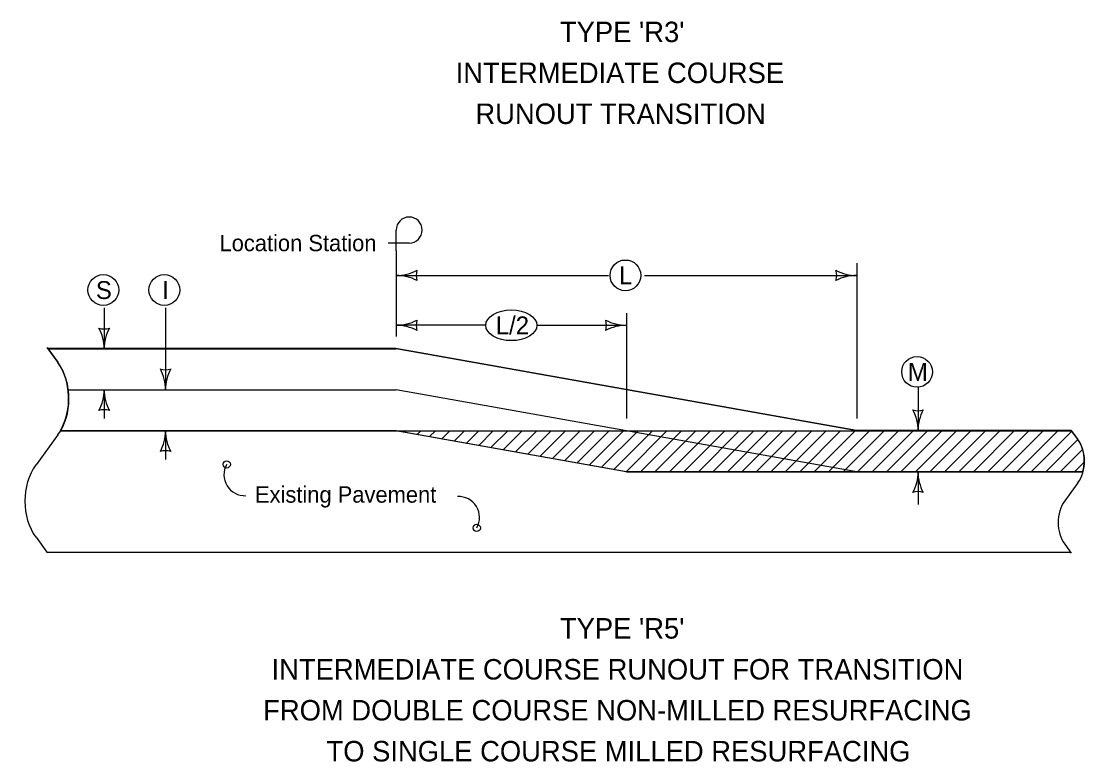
# Model space of a CAD drawing. Extents: x 10133 to 81668, y 2218 to 11018.
# Drawn here: x 19016 to 20057, y 2367 to 3091 of the extents above; entities that cross this region are included whole.
import ezdxf

# ---------------------------------------------------------------- set-up
doc = ezdxf.new("R2010")
doc.units = 0
for name, color, linetype in [('dsnNonPlotable', 7, 'Continuous'), ('dsnShtPlotShapeBatchPrint', 7, 'Continuous'), ('dsnStdBlock', 7, 'Continuous'), ('dsnStdBlockNotModified', 7, 'Continuous')]:
    doc.layers.add(name, color=color, linetype=linetype)

msp = doc.modelspace()

# ---------------------------------------------------------------- linework, layer by layer
at = {"layer": 'dsnNonPlotable'}
for p, q in [((19381.7, 2771.1), (19041.4, 2771.1)), ((19041.4, 2771.1), (19051.2, 2757.7)), ((19381.7, 2771.1), (19041.4, 2771.1)), ((19041.4, 2771.1), (19051.2, 2757.7)), ((19831.7, 2691.1), (19381.7, 2771.1)), ((19831.7, 2691.1), (19381.7, 2771.1)), ((19053.9, 2691.1), (19381.7, 2691.1)), ((19053.9, 2691.1), (19381.7, 2691.1)), ((19381.7, 2691.1), (19606.7, 2651.1)), ((19381.7, 2691.1), (19606.7, 2651.1)), ((20041.7, 2691.1), (19831.7, 2691.1)), ((20041.7, 2691.1), (19831.7, 2691.1)), ((20048, 2682.6), (20041.7, 2691.1)), ((20048, 2682.6), (20041.7, 2691.1)), ((19606.7, 2651.1), (20053.1, 2651.1)), ((19606.7, 2651.1), (20053.1, 2651.1))]:
    msp.add_line(p, q, dxfattribs=at)
for centre, major_axis, ratio, start_param in [((19025.3, 2722.4), (0, -50), 0.732645, 0.89539), ((19025.3, 2722.4), (0, -50), 0.732645, 0.89539), ((20032.4, 2661.4), (0, -30), 0.73263, 1.219806), ((20032.4, 2661.4), (0, -30), 0.73263, 1.219806)]:
    msp.add_ellipse(centre, major_axis=major_axis, ratio=ratio, start_param=start_param, end_param=2.356194, dxfattribs=at)
at = {"layer": 'dsnStdBlock'}
for p, q in [((19382, 2866.6), (19382, 2886.9)), ((19382, 2866.6), (19382, 2886.9)), ((19394.7, 2874.2), (19374.3, 2874.2)), ((19394.7, 2874.2), (19374.3, 2874.2)), ((19382, 2866.6), (19382, 2782.8)), ((19382, 2866.6), (19382, 2782.8)), ((19832, 2854.6), (19832, 2702.8)), ((19832, 2854.6), (19832, 2702.8)), ((19382, 2842.6), (19589.5, 2842.6)), ((19382, 2842.6), (19589.5, 2842.6)), ((19624.5, 2842.6), (19832, 2842.6)), ((19624.5, 2842.6), (19832, 2842.6)), ((19096.6, 2810.8), (19096.6, 2770.8)), ((19096.6, 2810.8), (19096.6, 2770.8)), ((19156.6, 2810.8), (19156.6, 2730.8)), ((19156.6, 2810.8), (19156.6, 2730.8)), ((19607, 2805.8), (19607, 2702.8)), ((19607, 2805.8), (19607, 2702.8)), ((19469.5, 2793.8), (19382, 2793.8)), ((19469.5, 2793.8), (19382, 2793.8)), ((19519.5, 2793.8), (19607, 2793.8)), ((19519.5, 2793.8), (19607, 2793.8)), ((19040.7, 2772), (19051.4, 2757.4)), ((19040.7, 2772), (19051.4, 2757.4)), ((19041.6, 2770.8), (19382, 2770.8)), ((19041.6, 2770.8), (19382, 2770.8)), ((19832, 2690.8), (19382, 2770.8)), ((19832, 2690.8), (19382, 2770.8)), ((19061.6, 2730.8), (19382, 2730.8)), ((19061.6, 2730.8), (19382, 2730.8)), ((19096.6, 2730.8), (19096.6, 2702.8)), ((19096.6, 2730.8), (19096.6, 2702.8)), ((19832, 2650.8), (19382, 2730.8)), ((19832, 2650.8), (19382, 2730.8)), ((19892, 2733.3), (19892, 2690.8)), ((19892, 2733.3), (19892, 2690.8)), ((19051.4, 2686.7), (19030, 2657.4)), ((19051.4, 2686.7), (19030, 2657.4)), ((19054.1, 2690.8), (19382, 2690.8)), ((19054.1, 2690.8), (19382, 2690.8)), ((19156.6, 2690.8), (19156.6, 2662.8)), ((19156.6, 2690.8), (19156.6, 2662.8)), ((19607, 2650.8), (19382, 2690.8)), ((19382, 2690.8), (19832, 2690.8)), ((19607, 2650.8), (19382, 2690.8)), ((19382, 2690.8), (19832, 2690.8)), ((19390.6, 2689.3), (19392.1, 2690.8)), ((19390.6, 2689.3), (19392.1, 2690.8)), ((19402.6, 2687.1), (19406.2, 2690.8)), ((19402.6, 2687.1), (19406.2, 2690.8)), ((19414.6, 2685), (19420.4, 2690.8)), ((19414.6, 2685), (19420.4, 2690.8)), ((19426.6, 2682.9), (19434.5, 2690.8)), ((19426.6, 2682.9), (19434.5, 2690.8)), ((19438.6, 2680.7), (19448.6, 2690.8)), ((19438.6, 2680.7), (19448.6, 2690.8)), ((19450.6, 2678.6), (19462.8, 2690.8)), ((19450.6, 2678.6), (19462.8, 2690.8)), ((19462.6, 2676.5), (19476.9, 2690.8)), ((19462.6, 2676.5), (19476.9, 2690.8)), ((19474.6, 2674.3), (19491.1, 2690.8)), ((19474.6, 2674.3), (19491.1, 2690.8)), ((19486.6, 2672.2), (19505.2, 2690.8)), ((19486.6, 2672.2), (19505.2, 2690.8)), ((19498.6, 2670.1), (19519.4, 2690.8)), ((19498.6, 2670.1), (19519.4, 2690.8)), ((19510.6, 2667.9), (19533.5, 2690.8)), ((19510.6, 2667.9), (19533.5, 2690.8)), ((19522.6, 2665.8), (19547.6, 2690.8)), ((19522.6, 2665.8), (19547.6, 2690.8)), ((19534.6, 2663.6), (19561.8, 2690.8)), ((19534.6, 2663.6), (19561.8, 2690.8)), ((19546.6, 2661.5), (19575.9, 2690.8)), ((19546.6, 2661.5), (19575.9, 2690.8)), ((19558.7, 2659.4), (19590.1, 2690.8)), ((19558.7, 2659.4), (19590.1, 2690.8)), ((19570.7, 2657.2), (19604.2, 2690.8)), ((19570.7, 2657.2), (19604.2, 2690.8)), ((19582.7, 2655.1), (19618.4, 2690.8)), ((19582.7, 2655.1), (19618.4, 2690.8)), ((19594.7, 2653), (19632.5, 2690.8)), ((19594.7, 2653), (19632.5, 2690.8)), ((19606.7, 2650.8), (19646.6, 2690.8)), ((19606.7, 2650.8), (19646.6, 2690.8)), ((19620.8, 2650.8), (19660.8, 2690.8)), ((19620.8, 2650.8), (19660.8, 2690.8)), ((19634.9, 2650.8), (19674.9, 2690.8)), ((19634.9, 2650.8), (19674.9, 2690.8)), ((19649.1, 2650.8), (19689.1, 2690.8)), ((19649.1, 2650.8), (19689.1, 2690.8)), ((19663.2, 2650.8), (19703.2, 2690.8)), ((19663.2, 2650.8), (19703.2, 2690.8)), ((19677.3, 2650.8), (19717.3, 2690.8)), ((19677.3, 2650.8), (19717.3, 2690.8)), ((19691.5, 2650.8), (19731.5, 2690.8)), ((19691.5, 2650.8), (19731.5, 2690.8)), ((19705.6, 2650.8), (19745.6, 2690.8)), ((19705.6, 2650.8), (19745.6, 2690.8)), ((19719.8, 2650.8), (19759.8, 2690.8)), ((19719.8, 2650.8), (19759.8, 2690.8)), ((19733.9, 2650.8), (19773.9, 2690.8)), ((19733.9, 2650.8), (19773.9, 2690.8)), ((19748.1, 2650.8), (19788.1, 2690.8)), ((19748.1, 2650.8), (19788.1, 2690.8)), ((19762.2, 2650.8), (19802.2, 2690.8)), ((19762.2, 2650.8), (19802.2, 2690.8)), ((19776.3, 2650.8), (19816.3, 2690.8)), ((19776.3, 2650.8), (19816.3, 2690.8)), ((19790.5, 2650.8), (19830.5, 2690.8)), ((19790.5, 2650.8), (19830.5, 2690.8)), ((19804.6, 2650.8), (19844.6, 2690.8)), ((19804.6, 2650.8), (19844.6, 2690.8)), ((19818.8, 2650.8), (19858.8, 2690.8)), ((19818.8, 2650.8), (19858.8, 2690.8)), ((19832, 2690.8), (20042, 2690.8)), ((19832, 2690.8), (20042, 2690.8)), ((19832.9, 2650.8), (19872.9, 2690.8)), ((19832.9, 2650.8), (19872.9, 2690.8)), ((19847.1, 2650.8), (19887.1, 2690.8)), ((19847.1, 2650.8), (19887.1, 2690.8)), ((19861.2, 2650.8), (19901.2, 2690.8)), ((19861.2, 2650.8), (19901.2, 2690.8)), ((19875.3, 2650.8), (19915.3, 2690.8)), ((19875.3, 2650.8), (19915.3, 2690.8)), ((19889.5, 2650.8), (19929.5, 2690.8)), ((19889.5, 2650.8), (19929.5, 2690.8)), ((19903.6, 2650.8), (19943.6, 2690.8)), ((19903.6, 2650.8), (19943.6, 2690.8)), ((19917.8, 2650.8), (19957.8, 2690.8)), ((19917.8, 2650.8), (19957.8, 2690.8)), ((19931.9, 2650.8), (19971.9, 2690.8)), ((19931.9, 2650.8), (19971.9, 2690.8)), ((19946, 2650.8), (19986, 2690.8)), ((19946, 2650.8), (19986, 2690.8)), ((19960.2, 2650.8), (20000.2, 2690.8)), ((19960.2, 2650.8), (20000.2, 2690.8)), ((19974.3, 2650.8), (20014.3, 2690.8)), ((19974.3, 2650.8), (20014.3, 2690.8)), ((19988.5, 2650.8), (20028.5, 2690.8)), ((19988.5, 2650.8), (20028.5, 2690.8)), ((20002.6, 2650.8), (20042.6, 2690.8)), ((20002.6, 2650.8), (20042.6, 2690.8)), ((20041.7, 2691.1), (20048.2, 2682.3)), ((20041.7, 2691.1), (20048.2, 2682.3)), ((20016.8, 2650.8), (20048.2, 2682.3)), ((20016.8, 2650.8), (20048.2, 2682.3)), ((20030.9, 2650.8), (20052.9, 2672.8)), ((20030.9, 2650.8), (20052.9, 2672.8)), ((20045, 2650.8), (20054.6, 2660.4)), ((20045, 2650.8), (20054.6, 2660.4)), ((19607, 2650.8), (20053.3, 2650.8)), ((19607, 2650.8), (20053.3, 2650.8)), ((19892, 2650.8), (19892, 2618.8)), ((19892, 2650.8), (19892, 2618.8)), ((20048.2, 2639.9), (20035.3, 2622.3)), ((20048.2, 2639.9), (20035.3, 2622.3)), ((19030, 2586.7), (19040.7, 2572)), ((19030, 2586.7), (19040.7, 2572)), ((19040.7, 2572), (20041.1, 2572)), ((19040.7, 2572), (20041.1, 2572)), ((20035.3, 2579.9), (20041.7, 2571.1)), ((20035.3, 2579.9), (20041.7, 2571.1))]:
    msp.add_line(p, q, dxfattribs=at)
for centre, radius in [((19606, 2842.6), 15), ((19606, 2842.6), 15), ((19095.8, 2828.3), 15), ((19095.8, 2828.3), 15), ((19155.4, 2828.3), 15), ((19155.4, 2828.3), 15), ((19891, 2748.3), 15), ((19891, 2748.3), 15), ((19216.4, 2657.9), 3.56), ((19216.4, 2657.9), 3.56), ((19460.7, 2595.8), 3.56), ((19460.7, 2595.8), 3.56)]:
    msp.add_circle(centre, radius, dxfattribs=at)
for centre, radius, start, end in [((19394.7, 2886.9), 12.7, 270, 180), ((19394.7, 2886.9), 12.7, 270, 180), ((19382, 2885.7), 43.2, 270, 298.0725), ((19382, 2885.7), 43.2, 270, 298.0725), ((19382, 2799.4), 43.2, 61.9275, 90), ((19382, 2799.4), 43.2, 61.9275, 90), ((19418.2, 2842.6), 16.7, 162.2666, 197.7334), ((19418.2, 2842.6), 16.7, 162.2666, 197.7334), ((19795.8, 2842.6), 16.7, 342.2666, 17.7333), ((19832, 2885.7), 43.2, 241.9275, 270), ((19795.8, 2842.6), 16.7, 342.2666, 17.7333), ((19832, 2885.7), 43.2, 241.9275, 270), ((19832, 2799.4), 43.2, 90, 118.0725), ((19832, 2799.4), 43.2, 90, 118.0725), ((19096.6, 2807), 16.7, 252.2666, 287.7333), ((19053.4, 2770.8), 43.2, 360, 28.0725), ((19096.6, 2807), 16.7, 252.2666, 287.7333), ((19053.4, 2770.8), 43.2, 360, 28.0725), ((19139.8, 2770.8), 43.2, 151.9275, 180), ((19139.8, 2770.8), 43.2, 151.9275, 180), ((19382, 2837), 43.2, 270, 298.0725), ((19382, 2837), 43.2, 270, 298.0725), ((19382, 2750.6), 43.2, 61.9275, 90), ((19382, 2750.6), 43.2, 61.9275, 90), ((19418.2, 2793.8), 16.7, 162.2666, 197.7334), ((19418.2, 2793.8), 16.7, 162.2666, 197.7334), ((19570.8, 2793.8), 16.7, 342.2666, 17.7333), ((19607, 2837), 43.2, 241.9275, 270), ((19570.8, 2793.8), 16.7, 342.2666, 17.7333), ((19607, 2837), 43.2, 241.9275, 270), ((19607, 2750.6), 43.2, 90, 118.0725), ((19607, 2750.6), 43.2, 90, 118.0725), ((19156.6, 2767), 16.7, 252.2666, 287.7333), ((19113.4, 2730.8), 43.2, 360, 28.0725), ((19156.6, 2767), 16.7, 252.2666, 287.7333), ((19113.4, 2730.8), 43.2, 360, 28.0725), ((19199.8, 2730.8), 43.2, 151.9275, 180), ((19199.8, 2730.8), 43.2, 151.9275, 180), ((19053.4, 2730.8), 43.2, 331.9275, 360), ((19053.4, 2730.8), 43.2, 331.9275, 360), ((19139.8, 2730.8), 43.2, 180, 208.0725), ((19139.8, 2730.8), 43.2, 180, 208.0725), ((19096.6, 2694.6), 16.7, 72.2666, 107.7334), ((19096.6, 2694.6), 16.7, 72.2666, 107.7334), ((19892, 2727), 16.7, 252.2666, 287.7333), ((19848.8, 2690.8), 43.2, 360, 28.0725), ((19892, 2727), 16.7, 252.2666, 287.7333), ((19848.8, 2690.8), 43.2, 360, 28.0725), ((19935.1, 2690.8), 43.2, 151.9275, 180), ((19935.1, 2690.8), 43.2, 151.9275, 180), ((19113.4, 2690.8), 43.2, 331.9275, 360), ((19113.4, 2690.8), 43.2, 331.9275, 360), ((19199.8, 2690.8), 43.2, 180, 208.0725), ((19199.8, 2690.8), 43.2, 180, 208.0725), ((19156.6, 2654.6), 16.7, 72.2666, 107.7334), ((19156.6, 2654.6), 16.7, 72.2666, 107.7334), ((19234.1, 2647.7), 20.4, 150.0683, 272.8436), ((19234.1, 2647.7), 20.4, 150.0683, 272.8436), ((19848.8, 2650.8), 43.2, 331.9275, 360), ((19848.8, 2650.8), 43.2, 331.9275, 360), ((19935.1, 2650.8), 43.2, 180, 208.0725), ((19935.1, 2650.8), 43.2, 180, 208.0725), ((19443, 2606.1), 20.4, 330.0683, 92.8436), ((19443, 2606.1), 20.4, 330.0683, 92.8436), ((19892, 2614.6), 16.7, 72.2666, 107.7334), ((19892, 2614.6), 16.7, 72.2666, 107.7334)]:
    msp.add_arc(centre, radius, start, end, dxfattribs=at)
msp.add_ellipse((19494.5, 2793.8), major_axis=(25, 0), ratio=0.6, dxfattribs=at)
msp.add_ellipse((19494.5, 2793.8), major_axis=(25, 0), ratio=0.6, dxfattribs=at)
for centre, major_axis, ratio in [((19025.5, 2722), (0, -50), 0.732645), ((19025.5, 2722), (0, -50), 0.732645), ((20032.6, 2661.1), (0, -30), 0.73263), ((20032.6, 2661.1), (0, -30), 0.73263), ((19055.8, 2622), (0, 50), 0.732645), ((19055.8, 2622), (0, 50), 0.732645), ((20050.9, 2601.1), (0, 30), 0.73263), ((20050.9, 2601.1), (0, 30), 0.73263)]:
    msp.add_ellipse(centre, major_axis=major_axis, ratio=ratio, start_param=0.785398, end_param=2.356194, dxfattribs=at)

# ---------------------------------------------------------------- texts
at = {"layer": 'dsnShtPlotShapeBatchPrint'}
msp.add_text('L/2', height=17.5, dxfattribs=at).set_placement((19479.3, 2785))
msp.add_text('L/2', height=17.5, dxfattribs=at).set_placement((19479.3, 2785))
at = {"layer": 'dsnStdBlockNotModified'}
for s, height, p in [("TYPE 'R3'", 20, (19542, 3070.5)), ("TYPE 'R3'", 20, (19542, 3070.5)), ('INTERMEDIATE COURSE', 20, (19440.1, 3030.5)), ('INTERMEDIATE COURSE', 20, (19440.1, 3030.5)), ('RUNOUT TRANSITION', 20, (19459.4, 2990.5)), ('RUNOUT TRANSITION', 20, (19459.4, 2990.5)), ('Location Station', 16, (19209.3, 2866.2)), ('Location Station', 16, (19209.3, 2866.2)), ('L', 17.5, (19599.7, 2833.8)), ('L', 17.5, (19599.7, 2833.8)), ('S', 17.5, (19088.5, 2819.5)), ('S', 17.5, (19088.5, 2819.5)), ('I', 17.5, (19153.3, 2819.5)), ('I', 17.5, (19153.3, 2819.5)), ('M', 17.5, (19882, 2739.5)), ('M', 17.5, (19882, 2739.5)), ('Existing Pavement', 16, (19244, 2620.5)), ('Existing Pavement', 16, (19244, 2620.5)), ("TYPE 'R5'", 20, (19542, 2487.7)), ("TYPE 'R5'", 20, (19542, 2487.7)), ('INTERMEDIATE COURSE RUNOUT FOR TRANSITION', 20, (19260.2, 2447.7)), ('INTERMEDIATE COURSE RUNOUT FOR TRANSITION', 20, (19260.2, 2447.7)), ('FROM DOUBLE COURSE NON-MILLED RESURFACING', 20, (19252, 2407.7)), ('FROM DOUBLE COURSE NON-MILLED RESURFACING', 20, (19252, 2407.7)), ('TO SINGLE COURSE MILLED RESURFACING', 20, (19313.9, 2367.7)), ('TO SINGLE COURSE MILLED RESURFACING', 20, (19313.9, 2367.7))]:
    msp.add_text(s, height=height, dxfattribs=at).set_placement(p)

doc.saveas('drawing.dxf')
